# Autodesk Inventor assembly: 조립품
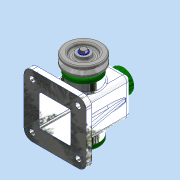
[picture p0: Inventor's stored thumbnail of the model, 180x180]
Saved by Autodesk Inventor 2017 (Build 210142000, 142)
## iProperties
Part Number: 조립품
Material: 일반
Document SubType Name: Assembly
Designer: MRC
Author: MRC
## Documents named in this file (14)
- C:\Users\MRC\Desktop\700907V1005\조립품.iam
- C:\Users\MRC\Desktop\700907V1005\본체.ipt
- C:\Users\MRC\Desktop\700907V1005\Ű 5 x 5 x 14.ipt
- C:\Users\MRC\Desktop\700907V1005\V-벨트풀리.ipt
- C:\Users\MRC\Desktop\700907V1005\뒤커버.ipt
- C:\Users\MRC\Desktop\700907V1005\멈춤링 15 x 1.ipt
- C:\Users\MRC\Desktop\700907V1005\베어링 15 x 35 x 11.ipt
- C:\Users\MRC\Desktop\700907V1005\볼트 M4 x 10.ipt
- C:\Users\MRC\Desktop\700907V1005\볼트 M6 x 12.ipt
- C:\Users\MRC\Desktop\700907V1005\상부캡.ipt
- C:\Users\MRC\Desktop\700907V1005\앞커버.ipt
- C:\Users\MRC\Desktop\700907V1005\오일실 15 25 7.ipt
- C:\Users\MRC\Desktop\700907V1005\와셔.ipt
- C:\Users\MRC\Desktop\700907V1005\축.ipt
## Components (2 placed, 2 different names)
1. Ű 5 x 5 x 14:1
2. V-벨트풀리:1
